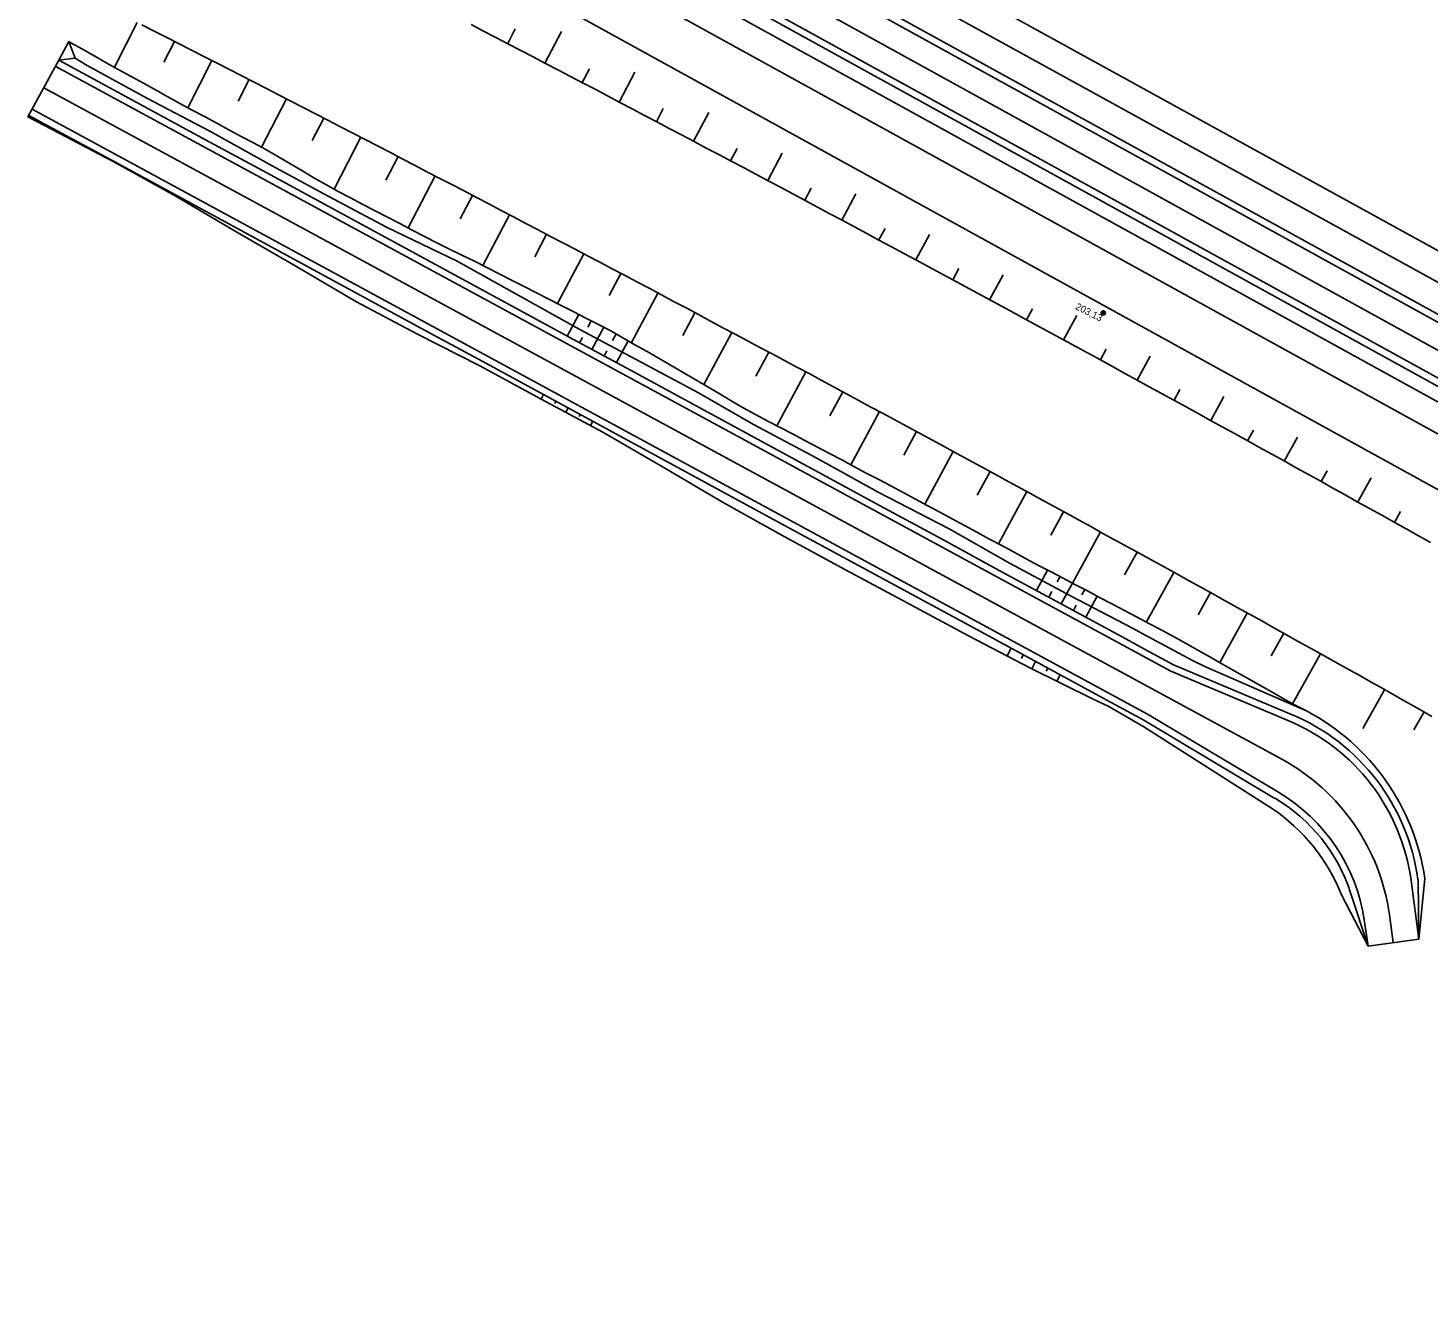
# Model space of a CAD drawing. Extents: x -552278 to -547230, y -1151007 to -1148251.
# Drawn here: x -550491.8 to -550391.5, y -1149028.3 to -1148936.3 of the extents above; entities that cross this region are included whole.
import ezdxf

# ---------------------------------------------------------------- set-up
doc = ezdxf.new("R2010")
doc.units = 0
doc.layers.add('SO221815_VYSKOPIS', color=7, linetype='Continuous')
doc.layers.add('u_trat navrh', color=7, linetype='Continuous')

# ---------------------------------------------------------------- blocks, each defined once
blk = doc.blocks.new('SO221824_VYSKOPIS')
at = {"layer": 'SO221815_VYSKOPIS'}
for p, q in [((1.2, -0.9), (-1.2, 0.9)), ((0.9, 1.2), (-0.9, -1.2)), ((0.9, 1.2), (0, 0)), ((0, 0), (1.2, -0.9))]:
    blk.add_line(p, q, dxfattribs=at)
blk.add_lwpolyline([(-0.9, -1.2), (0, 0), (-1.2, 0.9)], dxfattribs=at)
blk.add_circle((0, 0), 1.5, dxfattribs=at)
for start, end in [(145.362, 235.1538), (325.362, 55.1538)]:
    blk.add_arc((0, 0), 1.5, start, end, dxfattribs=at)

msp = doc.modelspace()

# ---------------------------------------------------------------- linework, layer by layer
at = {"layer": 'u_trat navrh'}
for p, q in [((-550460.23, -1148921.16), (-550253.98, -1149034.78)), ((-550461.07, -1148922.69), (-550254.82, -1149036.32)), ((-550461.8, -1148924.01), (-550255.55, -1149037.63)), ((-550440.69, -1148924.79), (-550379.29, -1148958.62)), ((-550462.76, -1148925.76), (-550256.51, -1149039.38)), ((-550441.65, -1148926.54), (-550251.93, -1149031.06)), ((-550464.45, -1148928.82), (-550344.48, -1148994.92)), ((-550442.86, -1148928.73), (-550253.14, -1149033.25)), ((-550442.62, -1148928.29), (-550252.89, -1149032.81)), ((-550484.01, -1148935.92), (-550485.64, -1148939.13)), ((-550457.47, -1148937.44), (-550456.93, -1148936.39)), ((-550454.81, -1148938.83), (-550453.62, -1148936.57)), ((-550489.64, -1148938.62), (-550488.92, -1148937.3)), ((-550488.92, -1148937.3), (-550488.45, -1148938.49)), ((-550481.34, -1148937.29), (-550482.1, -1148938.77)), ((-550489.64, -1148938.62), (-550491.84, -1148942.68)), ((-550409.97, -1148982.38), (-550489.88, -1148939.06)), ((-550488.45, -1148938.49), (-550489.64, -1148938.62)), ((-550478.66, -1148938.65), (-550480.39, -1148942.03)), ((-550475.99, -1148940.02), (-550476.78, -1148941.56)), ((-550452.14, -1148940.23), (-550451.62, -1148939.24)), ((-550449.48, -1148941.63), (-550448.35, -1148939.48)), ((-550411.64, -1148985.46), (-550491.54, -1148942.14)), ((-550473.32, -1148941.39), (-550475.11, -1148944.86)), ((-550446.82, -1148943.03), (-550446.32, -1148942.08)), ((-550470.65, -1148942.77), (-550471.49, -1148944.39)), ((-550444.16, -1148944.43), (-550443.07, -1148942.38)), ((-550467.99, -1148944.15), (-550469.91, -1148947.86)), ((-550441.5, -1148945.84), (-550441.02, -1148944.94)), ((-550465.32, -1148945.53), (-550466.19, -1148947.21)), ((-550438.84, -1148947.25), (-550437.8, -1148945.29)), ((-550462.66, -1148946.92), (-550464.6, -1148950.64)), ((-550436.19, -1148948.66), (-550435.73, -1148947.8)), ((-550460, -1148948.31), (-550460.87, -1148949.98)), ((-550433.53, -1148950.08), (-550432.52, -1148948.19)), ((-550457.34, -1148949.7), (-550459.24, -1148953.33)), ((-550454.68, -1148951.09), (-550455.53, -1148952.71)), ((-550430.88, -1148951.5), (-550430.43, -1148950.67)), ((-550428.23, -1148952.92), (-550427.25, -1148951.1)), ((-550452.02, -1148952.49), (-550453.9, -1148956.05)), ((-550449.37, -1148953.89), (-550450.2, -1148955.48)), ((-550425.58, -1148954.35), (-550425.15, -1148953.54)), ((-550422.94, -1148955.78), (-550421.98, -1148954)), ((-550446.71, -1148955.3), (-550448.6, -1148958.85)), ((-550453.2, -1148958.39), (-550452.37, -1148956.84)), ((-550444.06, -1148956.71), (-550444.93, -1148958.35)), ((-550420.29, -1148957.21), (-550419.86, -1148956.42)), ((-550417.65, -1148958.65), (-550416.7, -1148956.91)), ((-550451.72, -1148957.74), (-550451.48, -1148957.29)), ((-550451.44, -1148959.34), (-550450.59, -1148957.75)), ((-550441.41, -1148958.12), (-550443.41, -1148961.86)), ((-550452.32, -1148958.87), (-550452.12, -1148958.49)), ((-550449.96, -1148958.7), (-550449.71, -1148958.22)), ((-550449.67, -1148960.28), (-550448.84, -1148958.72)), ((-550450.56, -1148959.81), (-550450.36, -1148959.43)), ((-550438.76, -1148959.53), (-550439.69, -1148961.26)), ((-550415.01, -1148960.09), (-550414.59, -1148959.31)), ((-550412.38, -1148961.53), (-550411.44, -1148959.81)), ((-550436.12, -1148960.95), (-550438.18, -1148964.81)), ((-550409.73, -1148962.98), (-550409.31, -1148962.21)), ((-550454.9, -1148962.57), (-550455.07, -1148962.89)), ((-550454.02, -1148963.05), (-550454.1, -1148963.2)), ((-550433.47, -1148962.37), (-550434.4, -1148964.09)), ((-550407.09, -1148964.43), (-550406.16, -1148962.72)), ((-550453.14, -1148963.53), (-550453.31, -1148963.83)), ((-550453.14, -1148963.53), (-550453.31, -1148963.83)), ((-550452.26, -1148964), (-550452.34, -1148964.15)), ((-550430.83, -1148963.79), (-550432.88, -1148967.6)), ((-550451.38, -1148964.48), (-550451.54, -1148964.78)), ((-550428.19, -1148965.22), (-550429.1, -1148966.92)), ((-550404.46, -1148965.88), (-550404.04, -1148965.11)), ((-550401.83, -1148967.33), (-550400.88, -1148965.63)), ((-550425.55, -1148966.65), (-550427.59, -1148970.41)), ((-550422.91, -1148968.08), (-550423.83, -1148969.77)), ((-550399.2, -1148968.79), (-550398.77, -1148968.02)), ((-550396.57, -1148970.25), (-550395.61, -1148968.53)), ((-550420.27, -1148969.52), (-550422.31, -1148973.26)), ((-550417.64, -1148970.96), (-550418.55, -1148972.63)), ((-550393.94, -1148971.72), (-550393.5, -1148970.94)), ((-550415, -1148972.4), (-550417.01, -1148976.07)), ((-550412.37, -1148973.85), (-550413.27, -1148975.47)), ((-550418.79, -1148975.14), (-550419.58, -1148976.6)), ((-550417.9, -1148975.6), (-550418.1, -1148975.97)), ((-550417.01, -1148976.07), (-550417.82, -1148977.55)), ((-550409.74, -1148975.3), (-550411.7, -1148978.85)), ((-550418.49, -1148976.68), (-550418.7, -1148977.08)), ((-550416.13, -1148976.53), (-550416.34, -1148976.92)), ((-550415.24, -1148977), (-550416.06, -1148978.51)), ((-550407.12, -1148976.75), (-550408, -1148978.34)), ((-550416.74, -1148977.66), (-550416.94, -1148978.03)), ((-550404.49, -1148978.21), (-550406.46, -1148981.76)), ((-550401.87, -1148979.66), (-550402.76, -1148981.27)), ((-550421.4, -1148980.73), (-550421.69, -1148981.28)), ((-550420.53, -1148981.21), (-550420.66, -1148981.46)), ((-550399.24, -1148981.13), (-550401.24, -1148984.71)), ((-550419.65, -1148981.68), (-550419.91, -1148982.2)), ((-550418.77, -1148982.16), (-550418.88, -1148982.38)), ((-550409.78, -1148981.92), (-550401.32, -1148985.47)), ((-550407.48, -1148982.06), (-550400.2, -1148985.24)), ((-550417.89, -1148982.64), (-550418.12, -1148983.08)), ((-550409.97, -1148982.38), (-550401.51, -1148985.93)), ((-550394.65, -1148983.7), (-550396.21, -1148986.48)), ((-550391.82, -1148985.28), (-550392.55, -1148986.58)), ((-550411.9, -1148985.89), (-550402.5, -1148991.48)), ((-550411.64, -1148985.46), (-550402.24, -1148991.05)), ((-550411.9, -1148986.37), (-550402.75, -1148992.18)), ((-550392.18, -1149001.56), (-550392.25, -1148997.3)), ((-550392.18, -1149001.56), (-550391.76, -1148997.23)), ((-550395.82, -1149002.06), (-550397.08, -1148998.24)), ((-550392.18, -1149001.56), (-550392.75, -1148997.37)), ((-550395.82, -1149002.06), (-550397.73, -1148998.39)), ((-550395.82, -1149002.06), (-550396.1, -1149000.19)), ((-550392.18, -1149001.56), (-550395.82, -1149002.06))]:
    msp.add_line(p, q, dxfattribs=at)
for points in [[(-550255.07, -1149036.76), (-550461.31, -1148923.13)], [(-550483.68, -1148936.09), (-550482.79, -1148936.55), (-550481.9, -1148937), (-550481.01, -1148937.45), (-550480.12, -1148937.91), (-550479.23, -1148938.36), (-550478.34, -1148938.82), (-550477.45, -1148939.27), (-550476.56, -1148939.73), (-550475.68, -1148940.18), (-550474.79, -1148940.64), (-550473.9, -1148941.1), (-550473.01, -1148941.55), (-550472.12, -1148942.01), (-550471.24, -1148942.47), (-550470.35, -1148942.93), (-550469.46, -1148943.39), (-550468.57, -1148943.85), (-550467.69, -1148944.3), (-550466.8, -1148944.76), (-550465.91, -1148945.22), (-550465.03, -1148945.68), (-550464.14, -1148946.14), (-550463.26, -1148946.61), (-550462.37, -1148947.07), (-550461.48, -1148947.53), (-550460.6, -1148947.99), (-550459.71, -1148948.45), (-550458.83, -1148948.92), (-550457.94, -1148949.38), (-550457.06, -1148949.84), (-550456.18, -1148950.31), (-550455.29, -1148950.77), (-550454.41, -1148951.24), (-550453.52, -1148951.7), (-550452.64, -1148952.17), (-550451.76, -1148952.63), (-550450.87, -1148953.1), (-550449.99, -1148953.56), (-550449.11, -1148954.03), (-550448.22, -1148954.5), (-550447.34, -1148954.96), (-550446.46, -1148955.43), (-550445.58, -1148955.9), (-550444.69, -1148956.37), (-550443.81, -1148956.84), (-550442.93, -1148957.31), (-550442.05, -1148957.78), (-550441.17, -1148958.25), (-550440.29, -1148958.72), (-550439.41, -1148959.19), (-550438.52, -1148959.66), (-550437.64, -1148960.13), (-550436.76, -1148960.6), (-550435.88, -1148961.07), (-550435, -1148961.54), (-550434.12, -1148962.02), (-550433.24, -1148962.49), (-550432.37, -1148962.96), (-550431.49, -1148963.44), (-550430.61, -1148963.91), (-550429.73, -1148964.39), (-550428.85, -1148964.86), (-550427.97, -1148965.34), (-550427.09, -1148965.81), (-550426.21, -1148966.29), (-550425.34, -1148966.76), (-550424.46, -1148967.24), (-550423.58, -1148967.72), (-550422.7, -1148968.19), (-550421.83, -1148968.67), (-550420.95, -1148969.15), (-550420.07, -1148969.63), (-550419.2, -1148970.11), (-550418.32, -1148970.59), (-550417.44, -1148971.06), (-550416.57, -1148971.54), (-550415.69, -1148972.02), (-550414.82, -1148972.51), (-550413.94, -1148972.99), (-550413.07, -1148973.47), (-550412.19, -1148973.95), (-550411.32, -1148974.43), (-550410.44, -1148974.91), (-550409.57, -1148975.39), (-550408.69, -1148975.88), (-550407.82, -1148976.36), (-550406.95, -1148976.84), (-550406.07, -1148977.33), (-550405.2, -1148977.81), (-550404.32, -1148978.3), (-550403.45, -1148978.78), (-550402.58, -1148979.27), (-550401.71, -1148979.75), (-550400.83, -1148980.24), (-550399.96, -1148980.73), (-550399.09, -1148981.21), (-550398.22, -1148981.7), (-550397.35, -1148982.19), (-550396.47, -1148982.67), (-550395.6, -1148983.16), (-550394.73, -1148983.65), (-550393.86, -1148984.14), (-550392.99, -1148984.63), (-550392.12, -1148985.12), (-550391.25, -1148985.61)], [(-550460.09, -1148936.08), (-550459.2, -1148936.54), (-550458.31, -1148937), (-550457.42, -1148937.47), (-550456.53, -1148937.93), (-550455.65, -1148938.39), (-550454.76, -1148938.86), (-550453.87, -1148939.32), (-550452.98, -1148939.79), (-550452.1, -1148940.25), (-550451.21, -1148940.71), (-550450.32, -1148941.18), (-550449.44, -1148941.65), (-550448.55, -1148942.11), (-550447.67, -1148942.58), (-550446.78, -1148943.05), (-550445.89, -1148943.51), (-550445.01, -1148943.98), (-550444.12, -1148944.45), (-550443.24, -1148944.92), (-550442.35, -1148945.38), (-550441.47, -1148945.85), (-550440.58, -1148946.32), (-550439.7, -1148946.79), (-550438.82, -1148947.26), (-550437.93, -1148947.73), (-550437.05, -1148948.2), (-550436.16, -1148948.67), (-550435.28, -1148949.15), (-550434.4, -1148949.62), (-550433.51, -1148950.09), (-550432.63, -1148950.56), (-550431.75, -1148951.04), (-550430.87, -1148951.51), (-550429.98, -1148951.98), (-550429.1, -1148952.46), (-550428.22, -1148952.93), (-550427.34, -1148953.4), (-550426.46, -1148953.88), (-550425.57, -1148954.35), (-550424.69, -1148954.83), (-550423.81, -1148955.31), (-550422.93, -1148955.78), (-550422.05, -1148956.26), (-550421.17, -1148956.74), (-550420.29, -1148957.21), (-550419.41, -1148957.69), (-550418.53, -1148958.17), (-550417.65, -1148958.65), (-550416.77, -1148959.13), (-550415.89, -1148959.61), (-550415.01, -1148960.09), (-550414.13, -1148960.57), (-550413.26, -1148961.05), (-550412.38, -1148961.53), (-550411.5, -1148962.01), (-550410.62, -1148962.49), (-550409.74, -1148962.97), (-550408.86, -1148963.45), (-550407.99, -1148963.93), (-550407.11, -1148964.42), (-550406.23, -1148964.9), (-550405.36, -1148965.38), (-550404.48, -1148965.87), (-550403.6, -1148966.35), (-550402.73, -1148966.84), (-550401.85, -1148967.32), (-550400.97, -1148967.81), (-550400.1, -1148968.29), (-550399.22, -1148968.78), (-550398.35, -1148969.26), (-550397.47, -1148969.75), (-550396.6, -1148970.24), (-550395.72, -1148970.72), (-550394.85, -1148971.21), (-550393.97, -1148971.7), (-550393.1, -1148972.19), (-550392.22, -1148972.68), (-550391.35, -1148973.16)], [(-550488.92, -1148937.3), (-550488.81, -1148937.37), (-550487.93, -1148937.85), (-550487.06, -1148938.34), (-550486.19, -1148938.83), (-550485.32, -1148939.31), (-550484.45, -1148939.8), (-550483.57, -1148940.28), (-550482.7, -1148940.76), (-550481.83, -1148941.24), (-550480.95, -1148941.72), (-550480.08, -1148942.21), (-550479.2, -1148942.67), (-550478.32, -1148943.14), (-550477.44, -1148943.61), (-550476.56, -1148944.08), (-550475.68, -1148944.55), (-550474.8, -1148945.03), (-550473.94, -1148945.53), (-550473.07, -1148946.03), (-550472.21, -1148946.53), (-550471.35, -1148947.04), (-550470.49, -1148947.54), (-550469.61, -1148948.02), (-550468.73, -1148948.49), (-550467.85, -1148948.95), (-550466.96, -1148949.41), (-550466.08, -1148949.87), (-550465.2, -1148950.33), (-550464.31, -1148950.79), (-550463.42, -1148951.25), (-550462.54, -1148951.7), (-550461.65, -1148952.16), (-550460.75, -1148952.59), (-550459.85, -1148953.02), (-550458.96, -1148953.48), (-550458.07, -1148953.93), (-550457.19, -1148954.38), (-550456.3, -1148954.83), (-550455.41, -1148955.28), (-550454.52, -1148955.74), (-550453.63, -1148956.19), (-550452.74, -1148956.64), (-550451.86, -1148957.1), (-550450.97, -1148957.55), (-550450.08, -1148958.01), (-550449.21, -1148958.5), (-550448.35, -1148959), (-550447.48, -1148959.49), (-550446.62, -1148959.99), (-550445.76, -1148960.49), (-550444.89, -1148961), (-550444.03, -1148961.5), (-550443.17, -1148962), (-550442.31, -1148962.5), (-550441.45, -1148963.01), (-550440.59, -1148963.51), (-550439.72, -1148964), (-550438.84, -1148964.47), (-550437.95, -1148964.93), (-550437.07, -1148965.39), (-550436.19, -1148965.86), (-550435.31, -1148966.32), (-550434.42, -1148966.79), (-550433.54, -1148967.25), (-550432.66, -1148967.72), (-550431.78, -1148968.19), (-550430.89, -1148968.64), (-550430.01, -1148969.1), (-550429.13, -1148969.58), (-550428.26, -1148970.05), (-550427.38, -1148970.53), (-550426.5, -1148971), (-550425.62, -1148971.47), (-550424.74, -1148971.94), (-550423.87, -1148972.42), (-550422.99, -1148972.89), (-550422.11, -1148973.36), (-550421.24, -1148973.84), (-550420.36, -1148974.31), (-550419.48, -1148974.78), (-550418.59, -1148975.24), (-550417.71, -1148975.7), (-550416.83, -1148976.17), (-550415.94, -1148976.63), (-550415.06, -1148977.09), (-550414.18, -1148977.55), (-550413.29, -1148978.02), (-550412.41, -1148978.48), (-550411.53, -1148978.95), (-550410.65, -1148979.41), (-550409.77, -1148979.89), (-550408.9, -1148980.38), (-550408.03, -1148980.87), (-550407.17, -1148981.36), (-550406.3, -1148981.85), (-550405.43, -1148982.34), (-550404.56, -1148982.83), (-550403.69, -1148983.32), (-550402.82, -1148983.81), (-550401.96, -1148984.3), (-550401.09, -1148984.79), (-550400.2, -1148985.24)], [(-550409.76, -1148981.93), (-550412.1, -1148980.66), (-550413.19, -1148980.06), (-550417.59, -1148977.68), (-550421.99, -1148975.3), (-550426.38, -1148972.91), (-550430.78, -1148970.53), (-550435.17, -1148968.15), (-550439.57, -1148965.77), (-550443.96, -1148963.38), (-550448.36, -1148961), (-550452.75, -1148958.62), (-550457.15, -1148956.23), (-550461.55, -1148953.85), (-550465.94, -1148951.47), (-550470.34, -1148949.08), (-550474.73, -1148946.7), (-550479.13, -1148944.32), (-550483.52, -1148941.94), (-550487.92, -1148939.55), (-550489.64, -1148938.62)], [(-550407.48, -1148982.06), (-550408.4, -1148981.62), (-550411.66, -1148979.87), (-550412.75, -1148979.26), (-550417.11, -1148977), (-550421.46, -1148974.67), (-550425.85, -1148972.19), (-550430.92, -1148969.55), (-550435.33, -1148967.13), (-550439.86, -1148964.71), (-550443.79, -1148962.45), (-550447.95, -1148960.23), (-550452.36, -1148957.89), (-550456.72, -1148955.46), (-550461.09, -1148953.02), (-550466.15, -1148950.59), (-550470.65, -1148948.19), (-550474.34, -1148946.2), (-550478.82, -1148943.72), (-550483.28, -1148941.36), (-550487.6, -1148939), (-550488.45, -1148938.49)], [(-550402.01, -1148988.68), (-550490.71, -1148940.6)], [(-550411.9, -1148986.37), (-550414.4, -1148984.91), (-550415.53, -1148984.37), (-550420.01, -1148982.15), (-550424.45, -1148979.85), (-550428.86, -1148977.48), (-550433.26, -1148975.12), (-550437.66, -1148972.74), (-550442.03, -1148970.3), (-550446.34, -1148967.77), (-550450.66, -1148965.25), (-550455.07, -1148962.89), (-550459.47, -1148960.52), (-550463.93, -1148958.25), (-550468.35, -1148955.91), (-550472.66, -1148953.38), (-550476.99, -1148950.86), (-550481.3, -1148948.33), (-550485.68, -1148945.91), (-550490.1, -1148943.58), (-550491.84, -1148942.68)], [(-550411.89, -1148985.89), (-550414.24, -1148984.61), (-550415.34, -1148984.02), (-550419.73, -1148981.64), (-550424.13, -1148979.25), (-550428.53, -1148976.87), (-550432.92, -1148974.49), (-550437.32, -1148972.1), (-550441.71, -1148969.72), (-550446.11, -1148967.34), (-550450.5, -1148964.96), (-550454.9, -1148962.57), (-550459.29, -1148960.19), (-550463.69, -1148957.81), (-550468.09, -1148955.42), (-550472.48, -1148953.04), (-550476.88, -1148950.66), (-550481.27, -1148948.27), (-550485.67, -1148945.89), (-550490.06, -1148943.51), (-550491.78, -1148942.58)], [(-550394.03, -1149001.81), (-550394.3, -1148999.83)]]:
    msp.add_lwpolyline(points, dxfattribs=at)
for centre, radius, start, end in [((-550407.87, -1148999.61), 16.29, 8.3983, 61.9047), ((-550407.12, -1148999.3), 14.5, 7.6621, 67.2476), ((-550407.12, -1148999.3), 15, 7.6621, 67.2476), ((-550409.16, -1149001.87), 15, 7.816, 61.537), ((-550408.81, -1149002.09), 12.85, 8.5025, 59.2464), ((-550410.26, -1149003.39), 13.49, 21.7293, 56.1545), ((-550408.81, -1149002.09), 12.35, 18.1811, 59.2464)]:
    msp.add_arc(centre, radius, start, end, dxfattribs=at)

# ---------------------------------------------------------------- block references
at = {"layer": 'u_trat navrh', "xscale": 0.1, "yscale": 0.09999999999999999, "rotation": -31.851985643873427}
msp.add_blockref('SO221824_VYSKOPIS', (-550414.8, -1148956.72), dxfattribs=at)

# ---------------------------------------------------------------- texts
at = {"layer": 'u_trat navrh'}
msp.add_text('203,13', height=0.5, rotation=333.2568, dxfattribs=at).set_placement((-550416.84, -1148956.43))

doc.saveas('drawing.dxf')
